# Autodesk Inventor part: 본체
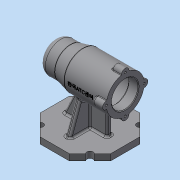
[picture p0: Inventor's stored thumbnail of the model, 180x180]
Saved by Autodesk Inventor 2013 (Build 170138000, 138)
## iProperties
Created: 2019-12
Part Number: 본체
Material: 일반
Document SubType Name: Modeling
Designer: Administrator
Density: 1 g/cm^3
Author: Administrator
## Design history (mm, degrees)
sketch "스케치1"
  geometry: L1 (23.196, 56)-(56, 23.196); L2 (56, 23.196)-(56, -23.196); L3 (56, -23.196)-(23.196, -56); L4 (23.196, -56)-(-23.196, -56); L5 (-23.196, -56)-(-56, -23.196); L6 (-56, -23.196)-(-56, 23.196); L7 (-56, 23.196)-(-23.196, 56); L8 (-23.196, 56)-(23.196, 56); 3 further points
  constraints: 16 end point, 1 coincident, 1 midpoint, 1 vertical alignment, 17 other
  dimensions: "d2" = 56 distance from line of point (0, 0) L8
extrude "돌출1" new body sketch "스케치1" distance "d3" = 10; taper "d4" = 0 deg
sketch "스케치2"
  geometry: L1 (-56, 80)-(56, 80); L2 (-56, 0)-(-56, 10) reference; L3 (-56, 80)-(-56, 110); L4 (-56, 110)-(11, 110); L5 (11, 110)-(31, 105); L6 (31, 105)-(56, 105); L7 (56, 80)-(56, 105); 1 further point
  constraints: 12 end point, 2 perpendicular, 1 collinear, 1 horizontal, 1 parallel, 1 vertical alignment
  dimensions: "d5" = 112 distance of L1.start L1.end; "d7" = 80 vertical distance of point (0, 0) L1.start; "d8" = 50 diameter of L6 L1; "d9" = 60 diameter of L4 L1; "d10" = 45 horizontal distance of L1.end L4.end; "d11" = 25 horizontal distance of L1.end L5.end
revolve "회전1" sketch "스케치2" stored, may be unused: angle "d12" = 90 deg
sketch "스케치4"
  geometry: L1 (-23.196, -56)-(23.196, -56) reference; L2 (4, -36)-(-4, -36); L3 (-4, -36)-(-4, 36); L4 (-4, 36)-(4, 36); L5 (4, 36)-(4, -36); L6 (4, -36)-(-4, 36); L7 (-4, -36)-(4, 36); 3 further points
  constraints: 12 end point, 3 midpoint, 2 parallel, 1 coincident, 1 horizontal, 1 perpendicular
  dimensions: "d19" = 8 distance of L3.end L4.end; "d21" = 20 distance between parallel lines of L1 L2
extrude "돌출2" join sketch "스케치4" distance "d22" = 70; taper "d23" = 0 deg
feature "면 기울기1" dims angle "d24" = 20 deg
sketch "스케치5"
  geometry: L1 (-56, 23.196)-(-56, -23.196) reference; L2 (56, -23.196)-(56, 23.196) reference; L3 (-38, 4)-(31, 4); L4 (31, 4)-(31, -4); L5 (31, -4)-(-38, -4); L6 (-38, -4)-(-38, 4); 2 further points
  constraints: 8 end point, 2 parallel, 1 horizontal, 1 horizontal alignment, 1 midpoint, 1 perpendicular
  dimensions: "d25" = 18 distance between parallel lines of L1 L6; "d26" = 25 distance between parallel lines of L2 L4; "d27" = 8 distance between parallel lines of L3 L5
extrude "돌출3" join sketch "스케치5" distance "d28" = 70; taper "d29" = 0 deg
feature "면 기울기2" dims angle "d30" = 25 deg
sketch "스케치6"
  geometry: C1 r 30 at (0, 0) reference; C2 r 6 at (0, 30); 1 further point
  constraints: 1 centre point, 1 vertical alignment
  dimensions: "d31" = 12 diameter of C2; "d33" = 30 distance of C1.centre C2.centre
extrude "돌출4" join sketch "스케치6" distance "d34" = 16; taper "d35" = 0 deg
fillet "모깎기1" dims "d36" = 3
fillet "모깎기2" dims "d37" = 1
sketch "스케치7"
  geometry: A1 r 6 centre (0, 0) between (5.998, 0.171) and (-5.998, 0.171) reference; 2 further points
  constraints: 1 coincident
hole "구멍1" sketch "스케치7" at (0, 0) diameter "d38" = 3.242; stored, may be unused: countersink angle "d42" = 90 deg, drill point angle "d44" = 118 deg; dims "d39" = 8, "d40" = 4, "d41" = 2, "d43" = 11
node "작업 평면1"
sketch "스케치8"
  geometry: L1 (33.5, 29.226)-(33.5, 6.771) reference; L2 (33.5, 5.998)-(33.5, -5.998) reference; 3 further points
  constraints: 1 horizontal alignment, 1 midpoint, 1 other
  dimensions: "d48" = 41 distance from line of point (-7.5, 0) L1
feature "엠보싱1" sketch "스케치8" dims "d5" = 112, "d7" = 80, "d8" = 50, "d9" = 60, "d10" = 45, "d11" = 25, "d49" = 0.5, "d50" = 0
sketch "스케치9"
  geometry: L1 (56, -23.196)-(56, 23.196) reference; L2 (0, 0)-(-39.598, 39.598); L3 (0, 0)-(13.566, 0); C1 r 56 at (0, 0); 2 further points
  constraints: 4 end point, 2 coincident, 1 centre point, 1 perpendicular
  dimensions: "d51" = 112 diameter of C1; "d54" = 135 deg angle of L3 L2; "d56" = 56 distance of L2.start L2.end
hole "구멍2" sketch "스케치9" at (-39.598, 39.598) diameter "d57" = 10; stored, may be unused: countersink angle "d61" = 90 deg, drill point angle "d63" = 0 deg; dims "d58" = 8, "d59" = 4, "d60" = 2, "d62" = 11
hole "구멍3" diameter "d69" = 42; stored, may be unused: countersink angle "d73" = 90 deg, drill point angle "d75" = 0 deg; dims "d67" = 10, "d68" = 10, "d70" = 8, "d71" = 4, "d72" = 2, "d74" = 15
hole "구멍4" diameter "d78" = 48; stored, may be unused: countersink angle "d82" = 90 deg, drill point angle "d84" = 0 deg; dims "d76" = 10, "d77" = 10, "d79" = 8, "d80" = 4, "d81" = 2, "d83" = 54
hole "구멍5" diameter "d87" = 42; stored, may be unused: countersink angle "d91" = 90 deg, drill point angle "d93" = 0 deg; dims "d85" = 10, "d86" = 10, "d88" = 8, "d89" = 4, "d90" = 2, "d92" = 12
hole "구멍6" diameter "d96" = 35; stored, may be unused: countersink angle "d100" = 90 deg, drill point angle "d102" = 0 deg; dims "d94" = 10, "d95" = 10, "d97" = 8, "d98" = 4, "d99" = 2, "d101" = 18
hole "구멍7" diameter "d105" = 21; stored, may be unused: countersink angle "d109" = 90 deg, drill point angle "d111" = 0 deg; dims "d103" = 10, "d104" = 10, "d106" = 8, "d107" = 32, "d108" = 4, "d110" = 7
fillet "모깎기3" dims "d112" = 3
fillet "모깎기4" dims "d113" = 0.3
fillet "모깎기5" dims "d114" = 0.3
fillet "모깎기6" dims "d115" = 0.3
fillet "모깎기7" dims "d116" = 3
chamfer "모따기1" distance "d117" = 1; stored, may be unused: second distance "d118" = 2, angle "d119" = 45 deg
fillet "모깎기8" dims "d120" = 10
fillet "모깎기9" dims "d121" = 3
fillet "모깎기10" dims "d122" = 3
fillet "모깎기11" dims "d123" = 3
node "솔리드1"
pattern_circular "원형 패턴1" dims "d46" = 360 deg
pattern_circular "원형 패턴2" dims angle "d65" = 360 deg
